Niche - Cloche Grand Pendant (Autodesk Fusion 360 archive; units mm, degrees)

design "Cloche Grand" references "Niche - Chief Architect - Luxe Single Pendant Cordset", "Cloche Grand - 10", "Luxe Single Pendant Cordset - 4ft Standard"
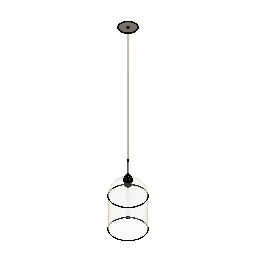
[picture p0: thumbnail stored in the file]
external_derived "ExternalDerived1" bodies "Body1"
external_derived "ExternalDerived2" bodies "Socket Body", "Shade Ring", "Shade Ring +Collar", "Socket", "Body1 (1)", "Metal Strain Relief", "Fabric Cord (1)", "Stem (Threaded)"
align "Align1"
external_derived "ExternalDerived3" bodies "T8-Bulb"
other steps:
derived_base_feature "Derived Base Feature1" bodies "Body1"
derived_base_feature "Derived Base Feature2" bodies "Socket Body", "Shade Ring", "Shade Ring +Collar", "Socket", "Body1 (1)", "Metal Strain Relief", "Fabric Cord (1)", "Stem (Threaded)"
derived_base_feature "Derived Base Feature3" bodies "T8-Bulb"
named bodies: "Body1", "Socket Body", "Shade Ring", "Shade Ring +Collar", "Socket", "Body1 (1)", "Metal Strain Relief", "Fabric Cord (1)", "Stem (Threaded)", "Cap (Threaded)", "5M Set Screw", "T8-Bulb"

design "Luxe Single Pendant Cordset - 4ft Standard" references "Luxe Canopy - Single Pendant Cordset"
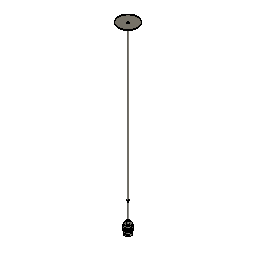
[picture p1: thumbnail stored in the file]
external_derived "ExternalDerived2" bodies "Cap (Threaded)"
move "Move1"
move "Move2"
offset_faces "OffsetFaces1" distance 1051.56
move "Move3"
move "Move4"
move "Move5"
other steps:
derived_base_feature "Derived Base Feature9" bodies "Socket Body", "Shade Ring", "Shade Ring +Collar", "Socket"
derived_base_feature "Derived Base Feature10" bodies "Body1"
derived_base_feature "Derived Base Feature12" bodies "Metal Strain Relief"
derived_base_feature "Derived Base Feature13" bodies "Fabric Cord (1)"
derived_base_feature "Derived Base Feature14" bodies "Stem (Threaded)"
derived_base_feature "Derived Base Feature15" bodies "Cap 9Threaded)", "Cap (Threaded)"
named bodies: "Socket Body", "Shade Ring", "Shade Ring +Collar", "Socket", "Metal Strain Relief", "Fabric Cord (1)", "Stem (Threaded)", "Cap 9Threaded)", "Body1", "Cap (Threaded)", "5M Set Screw"

design "Luxe Canopy - Single Pendant Cordset" references "M5 Set Screw", "Canopy Mounting Bar", "Plastic Strain Relief", "Canopy Mounting Bar Screw", "Luxe Cordset"
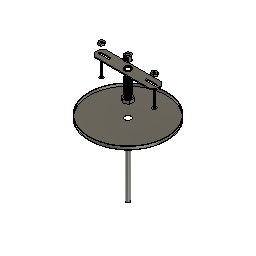
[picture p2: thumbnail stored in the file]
sketch "Sketch1" plane through (0, 0, 0) normal (0, 0, 1) x axis (1, 0, 0)
  circle C1 centre (0, 0) radius 63.5
  point P1 (0, 0)
  point P2 (0, 0)
  coincident P1 P2
  dimension "d1" diameter C1 = 127
extrude "Extrude1" new body sketch "Sketch1" along normal blind 5.08
shell "Shell1" innerThickness 0.762
hole "Hole1" HoleDepth 35.56 HoleDiameter 10.16 TipAngle 118
component_from_bodies "Body->Comp1"
component_insert "Component Insert1"
component_insert "Component Insert2"
component_insert "Component Insert3"
sketch "Sketch2" plane through (0, 0, 0) normal (0, 0, 1) x axis (1, 0, 0)
  circle C1 centre (0, 0) radius 3.175
  point P1 (0, 0)
  point P2 (0, 0)
  coincident P1 P2
  dimension "d8" diameter C1 = 6.35
extrude "Extrude2" new body sketch "Sketch2" along normal blind 127 and against normal blind 127 bodies "Fabric Cord"
component_insert "Component Insert4"
component_insert "Component Insert5"
position "Position1"
sketch "Sketch3" plane through (0, 0, 0.762) normal (0, 0, 1) x axis (-1, 0, 0)
  circle C1 centre (-0.0475, 0.2257) radius 5.08
  circle C2 centre (0, 0) radius 62.738
  circle C3 centre (0, 0) radius 4.826
  concentric C2 C3
  dimension "d13" diameter C3 = 9.652
extrude "Extrude3" new body sketch "Sketch3" profile of C3 along normal blind 25.4 bodies "Threaded Nipple"
shell "Shell2" innerThickness 1.27
thread "Thread1"
sketch "Sketch5" plane through (0, 0, 127) normal (0, 0, 1) x axis (-1, 0, 0)
  line L1 (-6.8191, 3.937) -> (0, 7.874)
  line L2 (-6.8191, -3.937) -> (-6.8191, 3.937)
  line L3 (0, -7.874) -> (-6.8191, -3.937)
  line L4 (6.8191, -3.937) -> (0, -7.874)
  line L5 (6.8191, 3.937) -> (6.8191, -3.937)
  line L6 (0, 7.874) -> (6.8191, 3.937)
  circle C1 centre (0, 0) radius 3.175
  point P2 (0, 0)
  point P9 (0, 0)
  point P3 (0, 7.874)
  coincident P2 P9
  dimension "d20" distance P3 P9 = 7.874
extrude "Extrude4" new body sketch "Sketch5" along normal blind 5.08 bodies "Hex Nut"
move "Move1"
thread "Thread2"
move "Move2" TranslateX 0 TranslateY 0 TranslateZ -55.88
move "Move3" TranslateX 0 TranslateY 0 TranslateZ 60.96
position "Position2"
sketch "Sketch6" plane through (0, 0, 0) normal (0, 0, 1) x axis (1, 0, 0)
  circle C1 centre (0, 0) radius 9.525
  point P1 (0, 0)
  point P2 (0, 0)
  coincident P1 P2
  dimension "d29" diameter C1 = 19.05
extrude "Extrude5" new body sketch "Sketch6" along normal blind 16.129 bodies "Metal Strain Relief"
move "Move4" TranslateX 0 TranslateY 0 TranslateZ -86.36
hole "Hole2" HoleDepth 10.16 HoleDiameter 5.08 TipAngle 118
hole "Hole3" HoleDepth 4.064 HoleDiameter 7.62 TipAngle 180
hole "Hole4" HoleDepth 12.192 HoleDiameter 9.144 TipAngle 180
thread "Thread3" ThreadOffset 0 ThreadLength 6.096
move "Move1" TranslateX 0 TranslateY 0 TranslateZ 68.58
move "Move5" TranslateX 0 TranslateY 0 TranslateZ 138.43
component_insert "Component Insert6"
external_derived "ExternalDerived1" bodies "5M Set Screw"
move "Move6" TranslateX 0 TranslateY 0 TranslateZ -185.42
copy_paste_bodies "CopyPasteBodies1"
move "Move7" TranslateX 0 TranslateY 0 TranslateZ -12.7
offset_faces "OffsetFaces1" distance -152.4
move "Move8"
component_from_bodies "Body->Comp2"
component_from_bodies "Body->Comp3"
component_from_bodies "Body->Comp4"
component_from_bodies "Body->Comp5"
hole "Hole1" HoleDepth 25.4 HoleDiameter 6.35 TipAngle 180
sketch "Sketch7" plane through (0, 0, 0) normal (0, 0, 1) x axis (1, 0, 0)
  line L1 (49.784, 3.9595) -> (52.07, 0)
  line L2 (45.212, 3.9595) -> (49.784, 3.9595)
  line L3 (42.926, 0) -> (45.212, 3.9595)
  line L4 (45.212, -3.9595) -> (42.926, 0)
  line L5 (49.784, -3.9595) -> (45.212, -3.9595)
  line L6 (52.07, 0) -> (49.784, -3.9595)
  point P2 (52.07, 0)
  point P8 (47.498, 0)
  dimension "d63" distance P2 P8 = 4.572
extrude "Extrude6" new body sketch "Sketch7" along normal blind 3.175 bodies "Mounting Hex Nut"
hole "Hole5" HoleDepth 25.4 HoleDiameter 3.81 TipAngle 180
thread "Thread4"
move "Move9"
component_from_bodies "Body->Comp6"
copy_paste "CopyPaste1"
move "Move10"
derived_base_feature "Derived Base Feature3" bodies "Stem (Threaded)", "Cap 9Threaded)"
move "Move11"
component_from_bodies "Body->Comp7"
component_from_bodies "Body->Comp8"
component_from_bodies "Body->Comp9"
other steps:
base_feature "Base Feature1"
base_feature "Base Feature1" bodies "Stem (Threaded)"
base_feature "Base Feature1" bodies "Cap 9Threaded)"
base_feature "Base Feature1" bodies "Fabric Cord"
base_feature "Base Feature1" bodies "Metal Strain Relief"
base_feature "Base Feature1" bodies "Mounting Hex Nut"
base_feature "Base Feature1" bodies "Hex Nut"
base_feature "Base Feature1" bodies "Fabric Cord (1)"
base_feature "Base Feature1" bodies "Threaded Nipple"
derived_base_feature "Derived Base Feature1" bodies "Socket Body", "Shade Ring", "Shade Ring +Collar", "Socket", "Rigid Stem"
derived_base_feature "Derived Base Feature2" bodies "5M Set Screw"
base_feature "Base Feature1" bodies "Fabric Cord", "Fabric Cord (1)"
create_component "CreateComponent1"
remove_body "RemoveBody1"
create_component "CreateComponent2"
remove_body "RemoveBody2"
create_component "CreateComponent3"
remove_body "RemoveBody3"
create_component "CreateComponent4"
remove_body "RemoveBody4"
create_component "CreateComponent5"
remove_body "RemoveBody5"
create_component "CreateComponent6"
remove_body "RemoveBody6"
create_component "CreateComponent7"
remove_body "RemoveBody7"
create_component "CreateComponent8"
remove_body "RemoveBody8"
create_component "CreateComponent9"
remove_body "RemoveBody9"
named bodies: "Fabric Cord", "Threaded Nipple", "Hex Nut", "Metal Strain Relief", "Socket Body", "Shade Ring", "Shade Ring +Collar", "Socket", "Rigid Stem", "5M Set Screw", "Fabric Cord (1)", "Mounting Hex Nut", "Stem (Threaded)", "Cap 9Threaded)"

design "M5 Set Screw"
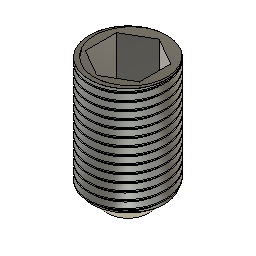
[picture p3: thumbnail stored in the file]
sketch "Sketch1" plane through (0, 0, 0) normal (0, 0, 1) x axis (1, 0, 0)
  circle C1 centre (0, 0) radius 2.5
  point P1 (0, 0)
  point P2 (0, 0)
  coincident P1 P2
  dimension "d1" diameter C1 = 5
extrude "Extrude1" new body sketch "Sketch1" along normal blind 8
sketch "Sketch2" plane through (0, 0, 8) normal (0, 0, 1) x axis (-1, 0, 0)
  line L1 (-1.7321, 1) -> (0, 2)
  line L2 (-1.7321, -1) -> (-1.7321, 1)
  line L3 (0, -2) -> (-1.7321, -1)
  line L4 (1.7321, -1) -> (0, -2)
  line L5 (1.7321, 1) -> (1.7321, -1)
  line L6 (0, 2) -> (1.7321, 1)
  circle C1 centre (0, 0) radius 2.5
  point P2 (0, 0)
  point P9 (0, 0)
  coincident P2 P9
extrude "Extrude2" cut sketch "Sketch2" profile of L1 L2 L3 L4 L5 L6 against normal blind 3
thread "Thread1" ThreadOffset 0.99 ThreadLength 7
chamfer "Chamfer1" distance 1.15

design "Luxe Cordset" references "M5 Set Screw"
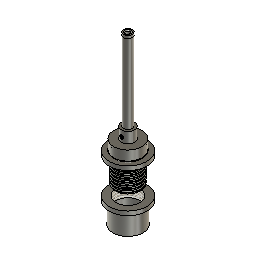
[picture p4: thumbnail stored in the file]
sketch "Sketch1" plane through (0, 0, 0) normal (0, 0, 1) x axis (1, 0, 0)
  circle C1 centre (0, 0) radius 20.6
  point P1 (0, 0)
  point P2 (0, 0)
  coincident P1 P2
  dimension "d11" diameter C1 = 41.2
extrude "Extrude1" new body sketch "Sketch1" along normal blind 14 bodies "Socket Body"
sketch "Sketch2" plane through (0, 0, 14) normal (0, 0, 1) x axis (-1, 0, 0)
  circle C1 centre (0, 0) radius 20.6
  circle C2 centre (0, 0) radius 9.6
  concentric C1 C2
  dimension "d3" diameter C2 = 19.2
extrude "Extrude2" add sketch "Sketch2" profile of C2 along normal blind 15.75
sketch "Sketch3" plane through (0, 0, 29.75) normal (0, 0, 1) x axis (-1, 0, 0)
  circle C1 centre (0, 0) radius 9.6
  circle C2 centre (0, 0) radius 5.75
  concentric C1 C2
  dimension "d6" diameter C2 = 11.5
extrude "Extrude3" new body sketch "Sketch3" profile of C2 along normal blind 114 bodies "Rigid Stem"
move "Move1"
sketch "Sketch4" plane through (0, 0, 203.75) normal (0, 0, 1) x axis (-1, 0, 0)
  circle C1 centre (0, 0) radius 5.75
  circle C2 centre (0, 0) radius 27.5
  dimension "d10" diameter C2 = 55
extrude "Extrude4" new body sketch "Sketch4" profile of C2 along normal blind 6 bodies "Shade Ring"
hole "Hole1" HoleDepth 25 HoleDiameter 42.75 TipAngle 118
sketch "Sketch5" plane through (0, 0, 0) normal (0, 0, 1) x axis (1, 0, 0)
  circle C1 centre (0, 0) radius 22
  point P1 (0, 0)
  point P2 (0, 0)
  coincident P1 P2
  dimension "d18" diameter C1 = 44
move "Move2"
copy_paste_bodies "CopyPasteBodies1"
move "Move3"
sketch "Sketch6" plane through (0, 0, 60) normal (0, 0, -1) x axis (1, 0, 0)
  circle C1 centre (0, 0) radius 20.6
  circle C2 centre (0, 0) radius 21.375
  circle C3 centre (0, 0) radius 20
  concentric C1 C2
  concentric C1 C3
  dimension "d21" diameter C2 = 42.75
  dimension "d24" diameter C3 = 40
cylinder_primitive "CylinderPrimitive1" Height 8 Diameter 42.75
thread "Thread1"
thread "Thread3"
hole "Hole2" HoleDepth 18 HoleDiameter 39 TipAngle 180
move "Move4"
move "Move5"
move "Move6"
hole "Hole3" HoleDepth 114 HoleDiameter 7.6 TipAngle 180
derived_base_feature "Derived Base Feature" bodies "Socket"
move "Move7"
scale "Scale1" ScaleX 1.2 ScaleY 1.2
move "Move8"
sketch "Sketch8" plane through (0, 0, -23.9827) normal (0, 0, -1) x axis (1, 0, 0)
  circle C1 centre (0, -0.036) radius 27.5
  circle C2 centre (0, -0.036) radius 22
  circle C3 centre (0, -0.036) radius 19.5
  dimension "d36" diameter C2 = 44
  dimension "d42" = -2.5
extrude "Extrude7" add sketch "Sketch8" profile of C2 C3 along normal blind 30
offset_faces "OffsetFaces1" distance 2.75
offset_faces "OffsetFaces2" distance -9
thread "Thread2"
move "Move9"
move "Move10"
move "Move11"
scale "Scale2" ScaleZ 1.2
move "Move12"
move "Move13"
move "Move14"
move "Move15"
move "Move16"
split_face "SplitFace1"
move "Move17"
move "Move18"
move "Move19"
move "Move20"
move "Move21"
move "Move22"
move "Move23"
move "Move24"
move "Move25"
move "Move26"
move "Move27"
thread "Thread4"
move "Move28"
move "Move29"
move "Move30"
hole "Hole4" HoleDepth 21 HoleDiameter 39.35 TipAngle 180
hole "Hole5" HoleDepth 9 HoleDiameter 5 TipAngle 180
move "Move31"
move "Move32"
hole "Hole6" HoleDepth 20 HoleDiameter 10 TipAngle 180
move_face "MoveFace3"
move "Move33"
move "Move34"
move "Move35"
move "Move36"
move "Move37"
thread "Thread5" ThreadOffset 0 ThreadLength 6
thread "Thread6" ThreadOffset 0 ThreadLength 6
move "Move38"
move "Move39"
move "Move40"
move "Move41"
component_insert "Component Insert"
thread "Thread7" ThreadOffset 0.5 ThreadLength 5.337
chamfer "Chamfer1" distance 0.5 distance 0.35
sketch "Sketch12" plane through (0, 0, 0) normal (0, 0, 1) x axis (1, 0, 0)
  circle C1 centre (0, 0) radius 6.35
  dimension "d60" diameter C1 = 12.7
extrude "Extrude8" new body sketch "Sketch12" along normal blind 115 bodies "Stem (Threaded)"
hole "Hole7" HoleDepth 115 HoleDiameter 9.65 TipAngle 118
thread "Thread8" ThreadOffset 0 ThreadLength 12.5
thread "Thread9" ThreadOffset 0 ThreadLength 12.5
sketch "Sketch13" plane through (0, 0, 0) normal (0, 0, 1) x axis (1, 0, 0)
  circle C1 centre (0, 0) radius 6.35
  point P1 (0, 0)
  point P2 (0, 0)
  coincident P1 P2
  dimension "d70" diameter C1 = 12.7
extrude "Extrude9" new body sketch "Sketch13" along normal blind 4 bodies "Cap 9Threaded)"
sketch "Sketch14" plane through (0, 0, 4) normal (0, 0, 1) x axis (-1, 0, 0)
  circle C1 centre (0, 0) radius 6.35
  circle C2 centre (0, 0) radius 4.5
  concentric C1 C2
  dimension "d73" diameter C2 = 9
extrude "Extrude10" add sketch "Sketch14" profile of C2 against normal blind 14
thread "Thread10"
hole "Hole8" HoleDepth 115 HoleDiameter 6.5 TipAngle 118 CSDiameter 9 CSAngle 90
move "Move42"
move "Move43"
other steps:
base_feature "Base Feature" bodies "Shade Ring +Collar"
named bodies: "Socket Body", "Shade Ring", "Shade Ring +Collar", "Socket", "Rigid Stem", "Stem (Threaded)", "Cap 9Threaded)"

design "Cloche Grand - 10"
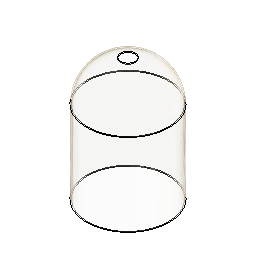
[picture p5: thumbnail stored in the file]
parameter "d3" = 12.7 (= "56fca90c-d675-46fc-97aa-0e1538f484da")
sketch "Sketch1" plane through (0, 0, 0) normal (0, 1, 0) x axis (1, 0, 0)
  line L1 (127, 254) -> (127, 0)
  line L2 (-127, 0) -> (-127, 254)
  line L3 (-123.825, 0) -> (-123.825, 254)
  line L4 (123.825, 254) -> (123.825, 0)
  line L5 (0, -123.825) -> (0, -127)
  line L6 (-123.825, 254) -> (-127, 254)
  line L7 (127, 254) -> (123.825, 254)
  arc A1 centre (0, 0) radius 127 clockwise from (127, 0) to (-127, 0)
  arc A2 centre (0, 0) radius 123.825 clockwise from (123.825, 0) to (-123.825, 0)
  point P1 (0, 0)
  point P2 (0, 0)
  point P8 (0, -127)
  point P9 (0, -123.825)
  coincident P1 P2
  vertical L1
  vertical L2
  midpoint A1 P8
  midpoint A2 P9
  vertical L5
  collinear L6 L7
  parallel L2 L3
  concentric A1 A2
  parallel L1 L4
  tangent L3 A2
  tangent A2 L4
revolve "Revolve1" sketch "Sketch1" AlongAngle 360
hole "Hole1" HoleDepth 12.7 HoleDiameter 44.958 TipAngle 118

design "Niche - Chief Architect - Luxe Single Pendant Cordset"
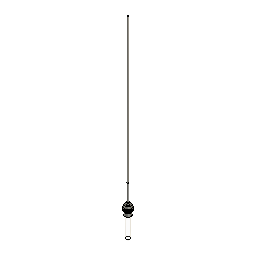
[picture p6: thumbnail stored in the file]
derived_base_feature "Derived Base Feature" bodies "Socket Body", "Shade Ring", "Shade Ring +Collar", "Socket", "Canopy", "Metal Strain Relief", "Fabric Cord (1)", "Stem (Threaded)"
remove_body "RemoveBody1"
remove_body "RemoveBody2"
split "Split1" bodies "Socket Body (1)"
remove_body "RemoveBody3"
align "Align1"
hole "Hole1" HoleDepth 19.05 HoleDiameter 8.89 TipAngle 118
combine "Combine1" bodies "Shade Ring"
split "Split2" bodies "Socket (1)"
remove_body "RemoveBody4"
split "Split3" bodies "Fabric Cord (1) (1)"
remove_body "RemoveBody5"
combine "Combine2" bodies "Socket Body"
align "Align2"
combine "Combine3" bodies "Metal Strain Relief"
sketch "Sketch1" plane through (0, 0, 0) normal (0, 1, 0) x axis (1, 0, 0)
  line L1 (13.1098, 24.9049) -> (-12.2902, 24.9049)
  line L2 (18.1898, 37.1766) -> (18.1898, 29.9849)
  line L3 (-17.3702, 29.9849) -> (-17.3702, 36.7132)
  line L4 (0, 132.969) -> (0, 24.9049)
  arc A1 centre (0, 86.36) radius 46.609 clockwise from (-22.6031, 45.5985) to (23.276, 45.979)
  arc A2 centre (-27.5302, 36.7132) radius 10.16 clockwise from (-22.6031, 45.5985) to (-17.3702, 36.7132)
  arc A3 centre (28.3498, 37.1766) radius 10.16 clockwise from (18.1898, 37.1766) to (23.276, 45.979)
  arc A4 centre (-12.2902, 29.9849) radius 5.08 clockwise from (-12.2902, 24.9049) to (-17.3702, 29.9849)
  arc A5 centre (13.1098, 29.9849) radius 5.08 clockwise from (18.1898, 29.9849) to (13.1098, 24.9049)
  point P5 (18.1898, 43.4469)
  point P3 (-17.3702, 24.9049)
  point P4 (18.1898, 24.9049)
  point P18 (0, 24.9049)
  point P19 (0, 132.969)
  horizontal L1
  vertical L2
  vertical L3
  tangent A1 A2
  tangent L3 A2
  coincident P5 L2
  coincident P5 A1
  tangent L2 A3
  tangent A1 A3
  equal A2 A3
  coincident P3 L1
  coincident P3 L3
  tangent L1 A4
  tangent L3 A4
  coincident P4 L1
  coincident P4 L2
  tangent L1 A5
  tangent L2 A5
  coincident L1 P18
  coincident A1 P19
  perpendicular L1 L4
  dimension "d4" diameter A1 = 93.218
  dimension "d5" distance P3 P4 = 35.56
  dimension "d6" distance P4 P5 = 18.542
  dimension "d7" radius A2 = 10.16
  dimension "d8" radius A4 = 5.08
  dimension "d9" radius A5 = 5.08
revolve "Revolve1" sketch "Sketch1" AlongAngle 360 bodies "G30-Bulb"
move "Move1"
sketch "Sketch2" plane through (0, 0, 0) normal (0, 1, 0) x axis (1, 0, 0)
  line L1 (12.7, 0) -> (-12.7, 0)
  line L2 (12.7, 152.4) -> (12.7, 0)
  line L3 (-12.7, 0) -> (-12.7, 152.4)
  line L4 (0, 165.1) -> (0, 0)
  arc A1 centre (0, 152.4) radius 12.7 clockwise from (-12.7, 152.4) to (12.7, 152.4)
  point P1 (0, 0)
  point P7 (0, 0)
  point P8 (0, 165.1)
  horizontal L1
  vertical L2
  vertical L3
  coincident P1 P7
  midpoint A1 P8
  perpendicular L1 L4
revolve "Revolve2" sketch "Sketch2" AlongAngle 360 bodies "T9-Bulb"
move "Move2"
sketch "Sketch3" plane through (0, 0, 0) normal (0, 1, 0) x axis (1, 0, 0)
  line L1 (12.7, 0) -> (-12.7, 0)
  line L2 (12.7, 254) -> (12.7, 0)
  line L3 (-12.7, 0) -> (-12.7, 254)
  line L4 (0, 266.7) -> (0, 0)
  arc A1 centre (0, 254) radius 12.7 clockwise from (-12.7, 254) to (12.7, 254)
  point P1 (0, 0)
  point P7 (0, 0)
  point P8 (0, 266.7)
  horizontal L1
  vertical L2
  vertical L3
  coincident P1 P7
  midpoint A1 P8
  perpendicular L1 L4
revolve "Revolve3" sketch "Sketch3" AlongAngle 360 bodies "T8-Bulb"
move "Move3"
move "Move4"
move "Move5"
sketch "Sketch4" plane through (0, 0, 0) normal (0, 1, 0) x axis (1, 0, 0)
  line L1 (15.875, -8.763) -> (-15.875, -8.763)
  line L2 (15.875, 22.987) -> (15.875, -8.763)
  line L3 (-15.875, 22.987) -> (15.875, 22.987)
  line L4 (-15.875, -8.763) -> (-15.875, 22.987)
  line L5 (0, 22.987) -> (0, -8.763)
  point P6 (0, -8.763)
  point P7 (0, 22.987)
  point P2 (-15.875, -8.763)
  point P3 (15.875, -8.763)
  point P5 (-15.875, 22.987)
  horizontal L1
  vertical L2
  horizontal L3
  vertical L4
  midpoint L1 P6
  midpoint L3 P7
  dimension "d13" distance P2 P3 = 31.75
  dimension "d14" distance P2 P5 = 31.75
revolve "Revolve4" sketch "Sketch4" AlongAngle 360 bodies "Bulb Extender"
move "Move6"
sketch "Sketch5" plane through (0, 0, 0) normal (0, 1, 0) x axis (1, 0, 0)
  line L1 (-12.7, 35.56) -> (12.7, 35.56)
  line L2 (-12.7, 5.08) -> (-12.7, 35.56)
  line L3 (12.7, 5.08) -> (-12.7, 5.08)
  line L4 (12.7, 35.56) -> (12.7, 5.08)
  line L5 (-12.7, 5.08) -> (12.7, 35.56)
  line L6 (12.7, 5.08) -> (-12.7, 35.56)
  line L7 (0, 35.56) -> (0, 5.08)
  point P6 (0, 20.32)
  point P7 (0, 5.08)
  point P8 (0, 35.56)
  horizontal L1
  perpendicular L1 L2
  parallel L1 L3
  parallel L2 L4
  coincident L5 P6
  coincident L6 P6
  midpoint L3 P7
  midpoint L1 P8
revolve "Revolve5" sketch "Sketch5" AlongAngle 360 bodies "Y-Spliter"
sketch "Sketch6" plane through (0, 0, 0) normal (0, 1, 0) x axis (1, 0, 0)
  line L1 (-55.88, 64.9514) -> (-21.59, 64.9514)
  line L2 (-55.88, 35.7414) -> (-55.88, 64.9514)
  line L3 (-21.59, 35.7414) -> (-55.88, 35.7414)
  line L4 (-21.59, 64.9514) -> (-21.59, 35.7414)
  line L5 (-55.88, 35.7414) -> (-21.59, 64.9514)
  line L6 (-21.59, 35.7414) -> (-55.88, 64.9514)
  line L7 (-38.735, 64.9514) -> (-38.735, 35.7414)
  point P6 (-38.735, 50.3464)
  point P7 (-38.735, 35.7414)
  point P8 (-38.735, 64.9514)
  point P4 (-55.88, 35.7414)
  point P5 (-21.59, 35.7414)
  point P2 (-21.59, 64.9514)
  horizontal L1
  perpendicular L1 L2
  parallel L1 L3
  parallel L2 L4
  coincident L5 P6
  coincident L6 P6
  midpoint L3 P7
  midpoint L1 P8
  dimension "d17" distance P4 P5 = 34.29
  dimension "d18" distance P2 P5 = 29.21
revolve "Revolve6" sketch "Sketch6" AlongAngle 360
chamfer "Chamfer1" distance 7.62
move "Move7"
mirror "Mirror1" mirrorStitchTolerance 0.1016
move "Move8"
combine "Combine4"
move "Move9"
sketch "Sketch7" plane through (0, 0, 0) normal (0, 1, 0) x axis (1, 0, 0)
  line L1 (-15.24, 40.64) -> (-15.24, 48.1816)
  line L2 (12.7, 38.1) -> (-12.7, 38.1)
  line L3 (15.24, 48.1816) -> (15.24, 40.64)
  line L4 (0, 100.1623) -> (0, 38.1)
  arc A1 centre (0, 76.2) radius 23.9623 clockwise from (-19.7282, 62.5988) to (19.7282, 62.5988)
  arc A2 centre (-40.64, 48.1816) radius 25.4 clockwise from (-19.7282, 62.5988) to (-15.24, 48.1816)
  arc A3 centre (40.64, 48.1816) radius 25.4 clockwise from (15.24, 48.1816) to (19.7282, 62.5988)
  arc A4 centre (-12.7, 40.64) radius 2.54 clockwise from (-12.7, 38.1) to (-15.24, 40.64)
  arc A5 centre (12.7, 40.64) radius 2.54 clockwise from (15.24, 40.64) to (12.7, 38.1)
  point P15 (0, 38.1)
  point P16 (0, 100.1623)
  parallel L1 L3
  tangent A1 A2
  tangent L1 A2
  tangent A1 A3
  tangent L3 A3
  tangent L1 A4
  tangent L2 A4
  tangent L2 A5
  tangent L3 A5
  midpoint L2 P15
  midpoint A1 P16
  perpendicular L2 L4
  dimension "d23" radius A2 = 25.4
  dimension "d24" radius A3 = 25.4
  dimension "d25" radius A4 = 2.54
  dimension "d26" radius A5 = 2.54
revolve "Revolve7" sketch "Sketch7" AlongAngle 360 bodies "A15-Bulb"
move "Move10"
copy_paste_bodies "CopyPasteBodies1"
copy_paste_bodies "CopyPasteBodies2"
move "Move11"
mirror "Mirror2" mirrorStitchTolerance 0.1016 bodies "A15-Bulb (1) (1)"
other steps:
base_feature "Base Feature1" bodies "Y-Spliter", "Bulb Extender", "Y-Spliter (1)", "Bulb Extender (1)"
base_feature "Base Feature2" bodies "A15-Bulb", "A15-Bulb (1)"
named bodies: "Socket Body", "Shade Ring", "Shade Ring +Collar", "Socket", "Canopy", "Metal Strain Relief", "Fabric Cord (1)", "Stem (Threaded)", "Adapter", "5M Set Screw", "Body1 (1)", "Socket Body (1)", "Socket (1)", "Fabric Cord (1) (1)", "G30-Bulb", "T9-Bulb", "T8-Bulb", "Bulb Extender", "Y-Spliter", "A15-Bulb", "Y-Spliter (1)", "Bulb Extender (1)", "A15-Bulb (1)", "A15-Bulb (1) (1)"

design "Plastic Strain Relief"
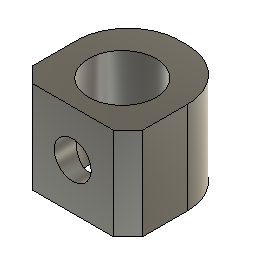
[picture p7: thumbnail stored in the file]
base_feature "Base Feature" bodies "strainrelief"
named bodies: "strainrelief"

design "Canopy Mounting Bar Screw"
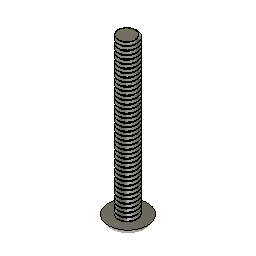
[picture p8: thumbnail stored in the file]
base_feature "Base Feature" bodies "screw1"
named bodies: "screw1"

design "Canopy Mounting Bar"
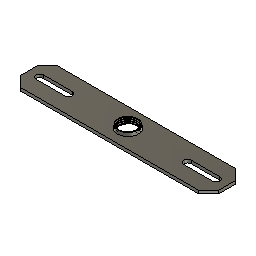
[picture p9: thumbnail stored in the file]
base_feature "Base Feature" bodies "mountingbar"
named bodies: "mountingbar"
